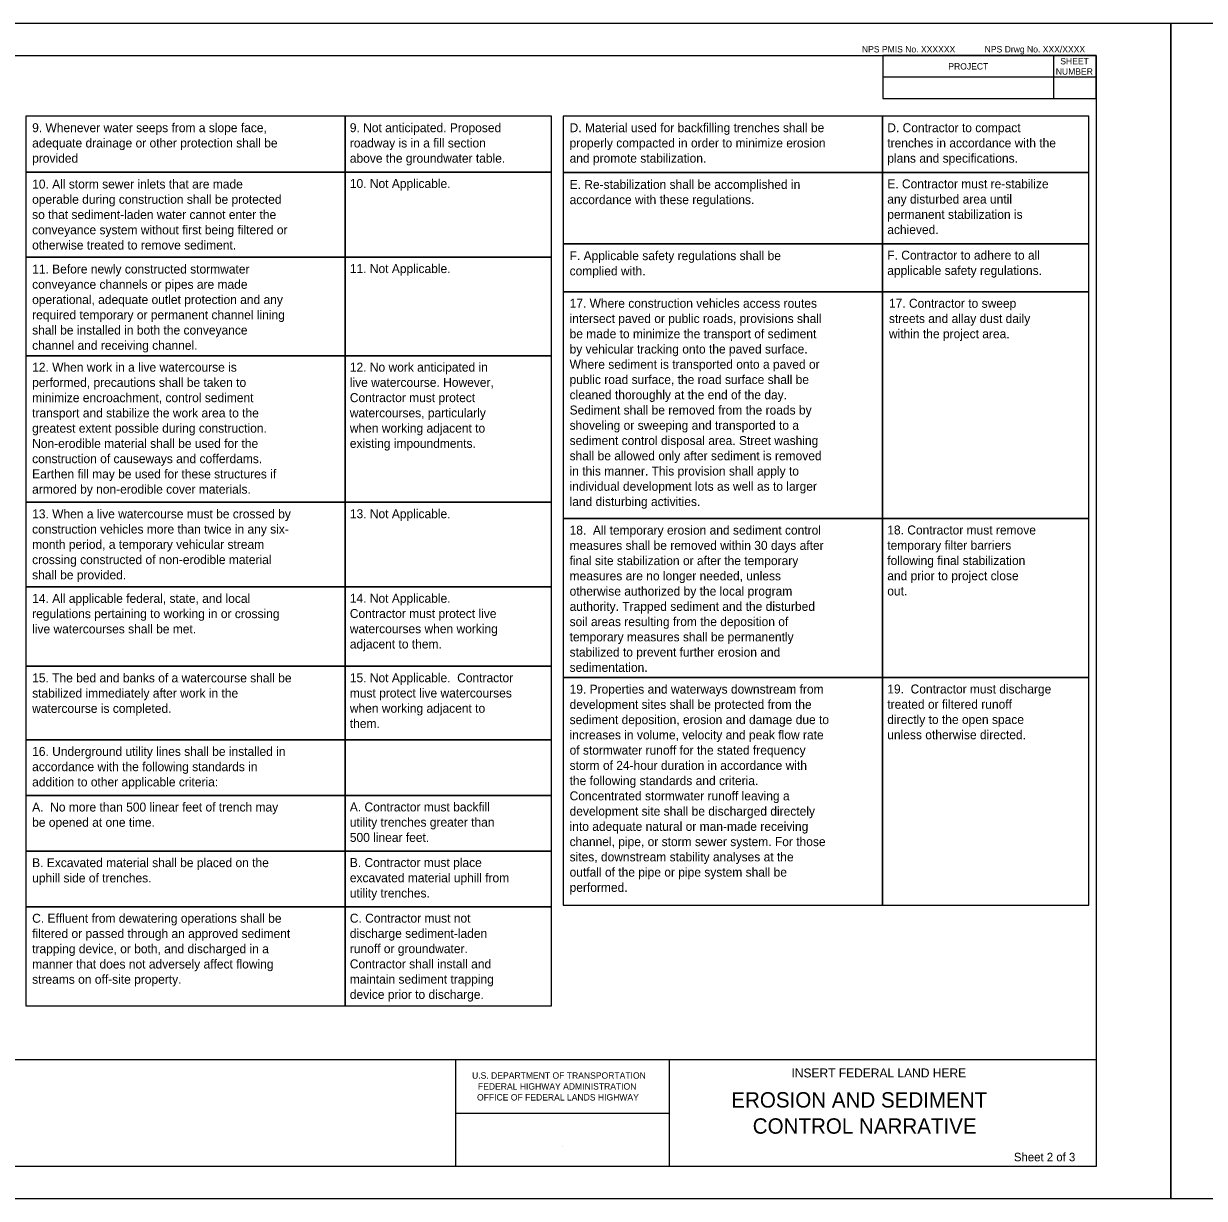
# Model space of a CAD drawing. Extents: x 20099.23 to 20103.48, y 6672.45 to 6674.37.
# Drawn here: x 20101.165 to 20102.086, y 6673.449 to 6674.366 of the extents above; entities that cross this region are included whole.
import ezdxf

# ---------------------------------------------------------------- set-up
doc = ezdxf.new("R2010")
doc.units = 0
for name, color, linetype in [('D_Details', 7, 'Continuous'), ('D_EFL_Handles', 7, 'Continuous'), ('D_Plot_Shape', 7, 'Continuous'), ('D_Sheet', 7, 'Continuous'), ('D_Sheet_Number', 7, 'Continuous')]:
    doc.layers.add(name, color=color, linetype=linetype)

msp = doc.modelspace()

# ---------------------------------------------------------------- linework, layer by layer
at = {"layer": 'D_Details'}
for points in [[(20101.41571, 6674.29368), (20101.16651, 6674.29368), (20101.16651, 6674.25015), (20101.41571, 6674.25015)], [(20101.57674, 6674.29368), (20101.41571, 6674.29368), (20101.41571, 6674.25015), (20101.57674, 6674.25015)], [(20101.83513, 6674.29368), (20101.58593, 6674.29368), (20101.58593, 6674.24987), (20101.83513, 6674.24987)], [(20101.99616, 6674.29368), (20101.83513, 6674.29368), (20101.83513, 6674.24987), (20101.99616, 6674.24987)], [(20101.41571, 6674.25015), (20101.16651, 6674.25015), (20101.16651, 6674.18376), (20101.41571, 6674.18376)], [(20101.57674, 6674.25015), (20101.41571, 6674.25015), (20101.41571, 6674.18376), (20101.57674, 6674.18376)], [(20101.83513, 6674.24987), (20101.58593, 6674.24987), (20101.58593, 6674.19422), (20101.83513, 6674.19422)], [(20101.99616, 6674.24987), (20101.83513, 6674.24987), (20101.83513, 6674.19422), (20101.99616, 6674.19422)], [(20101.83513, 6674.19422), (20101.58593, 6674.19422), (20101.58593, 6674.15668), (20101.83513, 6674.15668)], [(20101.99616, 6674.19422), (20101.83513, 6674.19422), (20101.83513, 6674.15668), (20101.99616, 6674.15668)], [(20101.41571, 6674.18376), (20101.16651, 6674.18376), (20101.16651, 6674.10686), (20101.41571, 6674.10686)], [(20101.57674, 6674.18376), (20101.41571, 6674.18376), (20101.41571, 6674.10686), (20101.57674, 6674.10686)], [(20101.83513, 6674.15668), (20101.58593, 6674.15668), (20101.58593, 6673.97978), (20101.83513, 6673.97978)], [(20101.99616, 6674.15668), (20101.83513, 6674.15668), (20101.83513, 6673.97978), (20101.99616, 6673.97978)], [(20101.41571, 6674.10686), (20101.16651, 6674.10686), (20101.16651, 6673.99246), (20101.41571, 6673.99246)], [(20101.57674, 6674.10686), (20101.41571, 6674.10686), (20101.41571, 6673.99246), (20101.57674, 6673.99246)], [(20101.41571, 6673.99246), (20101.16651, 6673.99246), (20101.16651, 6673.92651), (20101.41571, 6673.92651)], [(20101.57674, 6673.99246), (20101.41571, 6673.99246), (20101.41571, 6673.92651), (20101.57674, 6673.92651)], [(20101.83513, 6673.97978), (20101.58593, 6673.97978), (20101.58593, 6673.85571), (20101.83513, 6673.85571)], [(20101.99616, 6673.97978), (20101.83513, 6673.97978), (20101.83513, 6673.85571), (20101.99616, 6673.85571)], [(20101.41571, 6673.92651), (20101.16651, 6673.92651), (20101.16651, 6673.86448), (20101.41571, 6673.86448)], [(20101.57674, 6673.92651), (20101.41571, 6673.92651), (20101.41571, 6673.86448), (20101.57674, 6673.86448)], [(20101.41571, 6673.86448), (20101.16651, 6673.86448), (20101.16651, 6673.80709), (20101.41571, 6673.80709)], [(20101.57674, 6673.86448), (20101.41571, 6673.86448), (20101.41571, 6673.80709), (20101.57674, 6673.80709)], [(20101.83513, 6673.85571), (20101.58593, 6673.85571), (20101.58593, 6673.67801), (20101.83513, 6673.67801)], [(20101.99616, 6673.85571), (20101.83513, 6673.85571), (20101.83513, 6673.67801), (20101.99616, 6673.67801)], [(20101.41571, 6673.80709), (20101.16651, 6673.80709), (20101.16651, 6673.7637), (20101.41571, 6673.7637)], [(20101.57674, 6673.80709), (20101.41571, 6673.80709), (20101.41571, 6673.7637), (20101.57674, 6673.7637)], [(20101.41571, 6673.7637), (20101.16651, 6673.7637), (20101.16651, 6673.7203), (20101.41571, 6673.7203)], [(20101.57674, 6673.7637), (20101.41571, 6673.7637), (20101.41571, 6673.7203), (20101.57674, 6673.7203)], [(20101.41571, 6673.7203), (20101.16651, 6673.7203), (20101.16651, 6673.6769), (20101.41571, 6673.6769)], [(20101.57674, 6673.7203), (20101.41571, 6673.7203), (20101.41571, 6673.6769), (20101.57674, 6673.6769)], [(20101.41571, 6673.6769), (20101.16651, 6673.6769), (20101.16651, 6673.59946), (20101.41571, 6673.59946)], [(20101.57674, 6673.6769), (20101.41571, 6673.6769), (20101.41571, 6673.59946), (20101.57674, 6673.59946)]]:
    msp.add_lwpolyline(points, close=True, dxfattribs=at)
at = {"layer": 'D_Plot_Shape'}
for points in [[(20102.06018, 6674.36597), (20100.64352, 6674.36597), (20100.64352, 6673.44931), (20102.06018, 6673.44931)], [(20103.47685, 6674.36597), (20102.06018, 6674.36597), (20102.06018, 6673.44931), (20103.47685, 6673.44931)]]:
    msp.add_lwpolyline(points, close=True, dxfattribs=at)
at = {"layer": 'D_Sheet'}
for p, q in [((20101.96852, 6674.34097), (20101.96852, 6674.30764)), ((20102.00185, 6674.32431), (20101.83518, 6674.32431)), ((20100.70185, 6673.55764), (20102.00185, 6673.55764)), ((20101.50185, 6673.55764), (20101.50185, 6673.47431)), ((20101.66852, 6673.55764), (20101.66852, 6673.47431)), ((20101.50185, 6673.51571), (20101.66852, 6673.51571)), ((20101.58519, 6673.48993), (20101.58519, 6673.48993))]:
    msp.add_line(p, q, dxfattribs=at)
msp.add_lwpolyline([(20100.70185, 6673.47431), (20100.70185, 6673.55764), (20100.70185, 6674.34097), (20102.00185, 6674.34097), (20102.00185, 6673.55764), (20102.00185, 6673.47431), (20100.70185, 6673.47431)], dxfattribs=at)
msp.add_lwpolyline([(20102.00185, 6674.34097), (20101.83518, 6674.34097), (20101.83518, 6674.30764), (20102.00185, 6674.30764)], close=True, dxfattribs=at)

# ---------------------------------------------------------------- texts
at = {"layer": 'D_Details'}
for s, p in [('9. Whenever water seeps from a slope face, ', (20101.17145, 6674.28125)), ('9. Not anticipated. Proposed ', (20101.41936, 6674.28124)), ('D. Material used for backfilling trenches shall be ', (20101.59087, 6674.28125)), ('D. Contractor to compact ', (20101.83878, 6674.28124)), ('adequate drainage or other protection shall be ', (20101.17145, 6674.26935)), ('roadway is in a fill section ', (20101.41936, 6674.26934)), ('properly compacted in order to minimize erosion ', (20101.59087, 6674.26935)), ('trenches in accordance with the ', (20101.83878, 6674.26934)), ('provided', (20101.17145, 6674.25745)), ('above the groundwater table.', (20101.41936, 6674.25744)), ('and promote stabilization.', (20101.59087, 6674.25745)), ('plans and specifications.', (20101.83878, 6674.25744)), ('10. All storm sewer inlets that are made ', (20101.17145, 6674.23728)), ('10. Not Applicable.', (20101.41936, 6674.23771)), ('E. Re-stabilization shall be accomplished in ', (20101.59087, 6674.237)), ('E. Contractor must re-stabilize ', (20101.83878, 6674.23743)), ('operable during construction shall be protected ', (20101.17145, 6674.22538)), ('accordance with these regulations.', (20101.59087, 6674.2251)), ('any disturbed area until ', (20101.83878, 6674.22553)), ('so that sediment-laden water cannot enter the ', (20101.17145, 6674.21348)), ('permanent stabilization is ', (20101.83878, 6674.21363)), ('conveyance system without first being filtered or ', (20101.17145, 6674.20158)), ('achieved.', (20101.83878, 6674.20173)), ('otherwise treated to remove sediment.', (20101.17145, 6674.18968)), ('F. Applicable safety regulations shall be ', (20101.59087, 6674.18141)), ('F. Contractor to adhere to all ', (20101.83878, 6674.18178)), ('11. Before newly constructed stormwater ', (20101.17145, 6674.17095)), ('11. Not Applicable.', (20101.41936, 6674.17132)), ('complied with. ', (20101.59087, 6674.16951)), ('applicable safety regulations.', (20101.83878, 6674.16988)), ('conveyance channels or pipes are made ', (20101.17145, 6674.15905)), ('operational, adequate outlet protection and any ', (20101.17145, 6674.14715)), ('17. Where construction vehicles access routes ', (20101.59087, 6674.14425)), ('required temporary or permanent channel lining ', (20101.17145, 6674.13525)), ('17. Contractor to sweep ', (20101.84007, 6674.14425)), ('intersect paved or public roads, provisions shall ', (20101.59087, 6674.13235)), ('streets and allay dust daily ', (20101.84007, 6674.13235)), ('shall be installed in both the conveyance ', (20101.17145, 6674.12335)), ('be made to minimize the transport of sediment ', (20101.59087, 6674.12045)), ('within the project area.', (20101.84007, 6674.12045)), ('channel and receiving channel. ', (20101.17145, 6674.11145)), ('by vehicular tracking onto the paved surface. ', (20101.59087, 6674.10855)), ('12. When work in a live watercourse is ', (20101.17145, 6674.09438)), ('12. No work anticipated in ', (20101.41936, 6674.09442)), ('Where sediment is transported onto a paved or ', (20101.59087, 6674.09665)), ('performed, precautions shall be taken to ', (20101.17145, 6674.08248)), ('live watercourse. However, ', (20101.41936, 6674.08252)), ('public road surface, the road surface shall be ', (20101.59087, 6674.08475)), ('minimize encroachment, control sediment ', (20101.17145, 6674.07058)), ('cleaned thoroughly at the end of the day. ', (20101.59087, 6674.07285)), ('Contractor must protect ', (20101.41936, 6674.07062)), ('transport and stabilize the work area to the ', (20101.17145, 6674.05868)), ('watercourses, particularly ', (20101.41936, 6674.05872)), ('Sediment shall be removed from the roads by ', (20101.59087, 6674.06095)), ('greatest extent possible during construction. ', (20101.17145, 6674.04678)), ('when working adjacent to ', (20101.41936, 6674.04682)), ('shoveling or sweeping and transported to a ', (20101.59087, 6674.04905)), ('Non-erodible material shall be used for the ', (20101.17145, 6674.03488)), ('existing impoundments.', (20101.41936, 6674.03492)), ('sediment control disposal area. Street washing ', (20101.59087, 6674.03715)), ('shall be allowed only after sediment is removed ', (20101.59087, 6674.02525)), ('construction of causeways and cofferdams. ', (20101.17145, 6674.02298)), ('Earthen fill may be used for these structures if ', (20101.17145, 6674.01108)), ('in this manner. This provision shall apply to ', (20101.59087, 6674.01335)), ('armored by non-erodible cover materials. ', (20101.17145, 6673.99918)), ('individual development lots as well as to larger ', (20101.59087, 6674.00145)), ('land disturbing activities. ', (20101.59087, 6673.98955)), ('13. When a live watercourse must be crossed by ', (20101.17145, 6673.97993)), ('13. Not Applicable.', (20101.41936, 6673.98002)), ('construction vehicles more than twice in any six-', (20101.17145, 6673.96803)), ('18.  All temporary erosion and sediment control ', (20101.59087, 6673.96724)), ('18. Contractor must remove ', (20101.83878, 6673.96734)), ('month period, a temporary vehicular stream ', (20101.17145, 6673.95613)), ('measures shall be removed within 30 days after ', (20101.59087, 6673.95534)), ('temporary filter barriers ', (20101.83878, 6673.95544)), ('crossing constructed of non-erodible material ', (20101.17145, 6673.94423)), ('final site stabilization or after the temporary ', (20101.59087, 6673.94344)), ('following final stabilization ', (20101.83878, 6673.94354)), ('shall be provided.', (20101.17145, 6673.93233)), ('measures are no longer needed, unless ', (20101.59087, 6673.93154)), ('and prior to project close ', (20101.83878, 6673.93164)), ('14. All applicable federal, state, and local ', (20101.17145, 6673.91397)), ('14. Not Applicable. ', (20101.41936, 6673.91407)), ('otherwise authorized by the local program ', (20101.59087, 6673.91964)), ('out.', (20101.83878, 6673.91974)), ('authority. Trapped sediment and the disturbed ', (20101.59087, 6673.90774)), ('regulations pertaining to working in or crossing ', (20101.17145, 6673.90207)), ('Contractor must protect live ', (20101.41936, 6673.90217)), ('soil areas resulting from the deposition of ', (20101.59087, 6673.89584)), ('live watercourses shall be met.', (20101.17145, 6673.89017)), ('watercourses when working ', (20101.41936, 6673.89027)), ('adjacent to them.', (20101.41936, 6673.87837)), ('temporary measures shall be permanently ', (20101.59087, 6673.88394)), ('stabilized to prevent further erosion and ', (20101.59087, 6673.87204)), ('sedimentation.', (20101.59087, 6673.86014)), ('15. The bed and banks of a watercourse shall be ', (20101.17145, 6673.85194)), ('15. Not Applicable.  Contractor ', (20101.41936, 6673.85204)), ('19. Properties and waterways downstream from ', (20101.59087, 6673.84317)), ('19.  Contractor must discharge ', (20101.83878, 6673.84327)), ('stabilized immediately after work in the ', (20101.17145, 6673.84004)), ('must protect live watercourses ', (20101.41936, 6673.84014)), ('development sites shall be protected from the ', (20101.59087, 6673.83127)), ('treated or filtered runoff ', (20101.83878, 6673.83137)), ('watercourse is completed. ', (20101.17145, 6673.82814)), ('when working adjacent to ', (20101.41936, 6673.82824)), ('them.', (20101.41936, 6673.81634)), ('sediment deposition, erosion and damage due to ', (20101.59087, 6673.81937)), ('directly to the open space ', (20101.83878, 6673.81947)), ('increases in volume, velocity and peak flow rate ', (20101.59087, 6673.80747)), ('unless otherwise directed.', (20101.83878, 6673.80757)), ('16. Underground utility lines shall be installed in ', (20101.17145, 6673.79456)), ('of stormwater runoff for the stated frequency ', (20101.59087, 6673.79557)), ('accordance with the following standards in ', (20101.17145, 6673.78266)), ('storm of 24-hour duration in accordance with ', (20101.59087, 6673.78367)), ('addition to other applicable criteria:', (20101.17145, 6673.77076)), ('the following standards and criteria. ', (20101.59087, 6673.77177)), ('Concentrated stormwater runoff leaving a ', (20101.59087, 6673.75987)), ('A.  No more than 500 linear feet of trench may ', (20101.17145, 6673.75116)), ('A. Contractor must backfill ', (20101.41936, 6673.75126)), ('be opened at one time.', (20101.17145, 6673.73926)), ('utility trenches greater than ', (20101.41936, 6673.73936)), ('development site shall be discharged directely ', (20101.59087, 6673.74797)), ('into adequate natural or man-made receiving ', (20101.59087, 6673.73607)), ('500 linear feet.', (20101.41936, 6673.72746)), ('channel, pipe, or storm sewer system. For those ', (20101.59087, 6673.72417)), ('sites, downstream stability analyses at the ', (20101.59087, 6673.71227)), ('B. Excavated material shall be placed on the ', (20101.17145, 6673.70776)), ('B. Contractor must place ', (20101.41936, 6673.70786)), ('uphill side of trenches.', (20101.17145, 6673.69586)), ('excavated material uphill from ', (20101.41936, 6673.69596)), ('outfall of the pipe or pipe system shall be ', (20101.59087, 6673.70037)), ('utility trenches.', (20101.41936, 6673.68406)), ('performed.', (20101.59087, 6673.68847)), ('C. Effluent from dewatering operations shall be ', (20101.17145, 6673.66437)), ('C. Contractor must not ', (20101.41936, 6673.66446)), ('filtered or passed through an approved sediment ', (20101.17145, 6673.65247)), ('discharge sediment-laden ', (20101.41936, 6673.65256)), ('trapping device, or both, and discharged in a ', (20101.17145, 6673.64057)), ('runoff or groundwater. ', (20101.41936, 6673.64066)), ('manner that does not adversely affect flowing ', (20101.17145, 6673.62867)), ('Contractor shall install and ', (20101.41936, 6673.62876)), ('streams on off-site property.', (20101.17145, 6673.61677)), ('maintain sediment trapping ', (20101.41936, 6673.61686)), ('device prior to discharge. ', (20101.41936, 6673.60496))]:
    msp.add_text(s, height=0.007, dxfattribs=at).set_placement(p)
at = {"layer": 'D_EFL_Handles'}
msp.add_text('Sheet 2 of 3', height=0.00664, dxfattribs=at).set_placement((20101.93761, 6673.47824))
at = {"layer": 'D_Sheet'}
for s, height, p in [('SHEET', 0.005, (20101.97378, 6674.33414)), ('PROJECT', 0.005, (20101.88642, 6674.33014)), ('NUMBER', 0.005, (20101.97026, 6674.32614)), ('U.S. DEPARTMENT OF TRANSPORTATION', 0.005, (20101.51474, 6673.54268)), ('INSERT FEDERAL LAND HERE', 0.007, (20101.76404, 6673.54368)), ('FEDERAL HIGHWAY ADMINISTRATION', 0.005, (20101.51932, 6673.53418)), ('OFFICE OF FEDERAL LANDS HIGHWAY', 0.005, (20101.51861, 6673.52568)), ('EROSION AND SEDIMENT', 0.012, (20101.71705, 6673.52018)), ('CONTROL NARRATIVE', 0.012, (20101.73378, 6673.49978))]:
    msp.add_text(s, height=height, dxfattribs=at).set_placement(p)
at = {"layer": 'D_Sheet_Number'}
for s, p in [('NPS PMIS No. XXXXXX', (20101.819, 6674.34347)), ('NPS Drwg No. XXX/XXXX', (20101.91478, 6674.34347))]:
    msp.add_text(s, height=0.005, dxfattribs=at).set_placement(p)

doc.saveas('drawing.dxf')
